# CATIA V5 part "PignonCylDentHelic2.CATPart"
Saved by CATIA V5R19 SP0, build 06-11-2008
Part number: Roue Cyl Denture Hélicoïdale.1
Bounding box of the stored display mesh (mm): x -31.113 to 31.113, y -31.287 to 31.287, z 0 to 88
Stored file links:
  C:\Users\Martin\Documents\IFMA\Cfao\Projet S3\PignonCylDentHelic2.CATPart
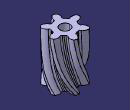
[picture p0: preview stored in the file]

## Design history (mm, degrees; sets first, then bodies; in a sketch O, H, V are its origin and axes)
External parameters (linked from other documents)
  External.Module = 7 mm
  External.Z = 6
  External.DiamPrimitif = 48.4974 mm {= External.ModuleApparent*External.Z}
  External.AnglePression = 20 deg
  External.x = 0
  External.DeportDenture = 0 mm {= External.x *External.ModuleApparent}
  External.DiamBase = 45.5727 mm {= External.DiamPrimitif *cos(External.AnglePression )}
  External.DiamPied = 38 mm
  External.DiamTete = 62.4974 mm {= External.DiamPrimitif +2*External.Module +2*External.DeportDenture}
  External.PhiPrimitif = 0.854 deg {= atan((sin(External.ThetaPrimitif*1rad)-External.ThetaPrimitif*cos(External.ThetaPrimitif*1rad))/(cos(External.ThetaPrimitif*1rad)+External.ThetaPrimitif*sin(External.ThetaPrimitif*1rad)))}
  External.PhiTete = 10.5878 deg {= atan((sin(External.ThetaTete*1rad)-External.ThetaTete*cos(External.ThetaTete*1rad))/(cos(External.ThetaTete*1rad)+External.ThetaTete*sin(External.ThetaTete*1rad)))}
  External.PhiSymetrie = 15 deg {= 180*1 deg/(2*External.Z )}
  External.CongePied = 2.66 mm {= 0.38*External.Module}
  External.AlphaCopie = 60 deg {= 360*1 deg/External.Z}
  External.AlphaSymetrieCopie = 30 deg {= External.AlphaCopie /2}
  External.LargeurDenture = 88 mm {= 88mm}
  External.ThetaPrimitif = 0.36397 {= sqrt(abs((External.DiamPrimitif*External.DiamPrimitif)/(External.DiamBase *External.DiamBase )-1))}
  External.ThetaTete = 0.938446 {= sqrt(abs((External.DiamTete*External.DiamTete)/(External.DiamBase *External.DiamBase )-1) )}
  External.Di = 47.035 mm {= (External.DiamBase +External.DiamPrimitif )/2}
  External.Thetai = 0.255358 {= sqrt(abs((External.Di*External.Di)/(External.DiamBase*External.DiamBase)-1))}
  External.Phii = 0.3061 deg {= atan((sin(External.Thetai*1rad)-External.Thetai*cos(External.Thetai*1rad))/(cos(External.Thetai*1rad)+External.Thetai*sin(External.Thetai*1rad)))}
  External.Dj = 55.4974 mm {= (External.DiamTete+External.DiamPrimitif)/2}
  External.Thetaj = 0.694971 {= sqrt(abs((External.Dj*External.Dj)/(External.DiamBase*External.DiamBase)-1))}
  External.Phij = 5.0207 deg {= atan((sin(External.Thetaj*1rad)-External.Thetaj*cos(External.Thetaj*1rad))/(cos(External.Thetaj*1rad)+External.Thetaj*sin(External.Thetaj*1rad)))}
  External.Dk = 46.3039 mm {= (External.Di+External.DiamBase)/2}
  External.Thetak = 0.179851 {= sqrt(abs((External.Dk*External.Dk)/(External.DiamBase*External.DiamBase)-1))}
  External.Phik = 0.109 deg {= atan((sin(External.Thetak*1rad)-External.Thetak*cos(External.Thetak*1rad))/(cos(External.Thetak*1rad)+External.Thetak*sin(External.Thetak*1rad)))}
  External.Dl = 47.7662 mm {= (External.DiamPrimitif+External.Di)/2}
  External.Thetal = 0.31398 {= sqrt(abs((External.Dl*External.Dl)/(External.DiamBase*External.DiamBase)-1))}
  External.Phil = 0.5585 deg {= atan((sin(External.Thetal*1rad)-External.Thetal*cos(External.Thetal*1rad))/(cos(External.Thetal*1rad)+External.Thetal*sin(External.Thetal*1rad)))}
  External.Dm = 51.9974 mm {= (External.Dj+External.DiamPrimitif)/2}
  External.Thetam = 0.549392 {= sqrt(abs((External.Dm*External.Dm)/(External.DiamBase*External.DiamBase)-1))}
  External.Phim = 2.6938 deg {= atan((sin(External.Thetam*1rad)-External.Thetam*cos(External.Thetam*1rad))/(cos(External.Thetam*1rad)+External.Thetam*sin(External.Thetam*1rad)))}
  External.Dn = 58.9974 mm {= (External.DiamTete+External.Dj)/2}
  External.Thetan = 0.822153 {= sqrt(abs((External.Dn*External.Dn)/(External.DiamBase*External.DiamBase)-1))}
  External.Phin = 7.6805 deg {= atan((sin(External.Thetan*1rad)-External.Thetan*cos(External.Thetan*1rad))/(cos(External.Thetan*1rad)+External.Thetan*sin(External.Thetan*1rad)))}
  External.AngleHelice = 30 deg
  External.ModuleApparent = 8.0829 mm {= External.Module /cos(External.AngleHelice )}
  External.SensDenture = -1
  External.LargeurDent = 45 mm {= round(PI*External.Module /sin(External.AngleHelice )/1mm)*1mm+1mm}
Body1 (main body)
  Sketch1 "EsquisseDent" on xy-plane, origin (0, 0, 0), H (1, 0, 0), V (0, 1, 0)
    construction circle A1 centre (0, 0) radius 24.2487
    construction circle A2 centre (0, 0) radius 22.7863
    construction circle A3 centre (0, 0) radius 19
    construction circle A4 centre (0, 0) radius 31.2487
    point P1 (22.7863, 0)
    construction line L1 (22.7863, 0) -> (0, 0)
    point P2 (24.246, 0.3614)
    construction line L2 (24.246, 0.3614) -> (0, 0)
    point P3 (30.7167, 5.7417)
    construction line L3 (30.7167, 5.7417) -> (0, 0)
    construction line L4 (22.7863, 0) -> (22.7863, 3.9367)
    point P4 (22.7863, 0)
    point P6 (21.3267, 0.3614)
    construction line L5 (30.7167, 5.7417) -> (24.246, 0.3614)
    point P7 (27.4814, 3.0515)
    point P8 (18.0913, 3.0515)
    spline S1 through (18.0913, 3.0515) (21.3267, 0.3614) (22.7863, 0) (23.1519, 0.044) (23.5172, 0.1257) (23.882, 0.2328) (24.246, 0.3614) (25.97, 1.2219) (27.6422, 2.4285) (29.2341, 3.9424) (30.7167, 5.7417)
    construction line L6 (0, 0) -> (5.0738, 1.4409)
    spline S2 through (16.9948, 6.9125) (18.3334, 10.9016) (19.3852, 11.9763) (19.7194, 12.1309) (20.073, 12.2535) (20.4397, 12.3541) (20.817, 12.436) (22.7359, 12.61) (24.7927, 12.4625) (26.9427, 12.0111) (29.1496, 11.2597)
    arc A5 centre (21.5111, -2.5354) radius 2.66 from (22.1075, 0.0569) to (18.8694, -2.224) ccw
    point P11 (18.8694, -2.224)
    arc A6 centre (0, 0) radius 31.2487 from (30.7167, 5.7417) to (29.1496, 11.2597) ccw
    point P13 (29.1496, 11.2597)
    arc A7 centre (16.9678, 13.4629) radius 2.66 from (14.884, 11.8096) to (18.8376, 11.571) ccw
    point P15 (14.884, 11.8096)
    construction line L7 (0, 0) -> (2.9832, 3.0735)
    construction line L8 (0, 0) -> (4.9704, -1.2527)
    point P19 (13.2333, 13.6338)
    arc A8 centre (0, 0) radius 19 from (14.884, 11.8096) to (13.2333, 13.6338) ccw
    point P20 (18.4238, -4.6435)
    arc A9 centre (0, 0) radius 19 from (18.4238, -4.6435) to (18.8694, -2.224) ccw
    line L9 (13.2333, 13.6338) -> (0, 0)
    line L10 (18.4238, -4.6435) -> (0, 0)
    construction circle A10 centre (0, 0) radius 23.5175
    construction line L11 (0, 0) -> (2.5698, 0.0137)
    point P22 (23.5172, 0.1257)
    construction circle A11 centre (0, 0) radius 27.7487
    construction line L12 (0, 0) -> (4.0036, 0.3517)
    point P24 (27.6422, 2.4285)
    point P25 (27.6422, 2.4285)
    point P26 (24.7927, 12.4625)
    point P27 (20.073, 12.2535)
    construction circle A12 centre (0, 0) radius 23.1519
    construction line L13 (0, 0) -> (48.2618, 0.0918)
    point P29 (19.7194, 12.1309)
    construction line L14 (0, 0) -> (61.5448, 17.478)
    point P31 (23.1519, 0.044)
    construction circle A13 centre (0, 0) radius 23.8831
    construction line L15 (0, 0) -> (57.3607, 0.5591)
    point P33 (23.882, 0.2328)
    point P34 (20.4397, 12.3541)
    construction circle A14 centre (0, 0) radius 25.9987
    construction line L16 (0, 0) -> (65.6381, 3.0883)
    point P36 (25.97, 1.2219)
    point P37 (22.7359, 12.61)
    construction circle A15 centre (0, 0) radius 29.4987
    axis line L17 (0, 0) -> (58.8185, 7.9321)
    point P39 (26.9427, 12.0111)
    point P40 (29.2341, 3.9424)
    point P42 (18.0913, 3.0515)
    point P43 (21.3267, 0.3614)
    point P44 (22.7863, 0)
    point P45 (24.246, 0.3614)
    point P46 (30.7167, 5.7417)
    point P47 (29.1496, 11.2597)
    point P48 (16.9948, 6.9125)
    point P49 (20.817, 12.436)
    point P50 (19.3852, 11.9763)
    point P51 (18.3334, 10.9016)
    point P52 (23.5172, 0.1257)
    point P53 (27.6422, 2.4285)
    point P54 (20.073, 12.2535)
    point P55 (24.7927, 12.4625)
    point P56 (23.1519, 0.044)
    point P57 (19.7194, 12.1309)
    point P58 (23.882, 0.2328)
    point P59 (20.4397, 12.3541)
    point P60 (25.97, 1.2219)
    point P61 (22.7359, 12.61)
    point P62 (29.2341, 3.9424)
    point P63 (26.9427, 12.0111)
    radius A1 = 24.2487 {= External.DiamPrimitif /2}
    radius A2 = 22.7863 {= External.DiamBase /2}
    radius A3 = 19 {= External.DiamPied /2}
    radius A4 = 31.2487 {= External.DiamTete /2}
    angle L2 L1 = 0.854 {= External.PhiPrimitif}
    angle L3 L1 = 10.5878 {= External.PhiTete}
    angle L4 L1 = 90
    radius A5 = 2.66 {= External.CongePied}
    radius A7 = 2.66 {= External.CongePied}
    angle L7 L6 = 30 {= External.AlphaSymetrieCopie}
    angle L2 L6 = 15 {= External.PhiSymetrie}
    radius A10 = 23.5175 {= External.Di /2}
    angle L11 L1 = 0.3061 {= External.Phii}
    radius A11 = 27.7487 {= External.Dj /2}
    angle L12 L1 = 5.0207 {= External.Phij}
    radius A12 = 23.1519 {= External.Dk/2}
    angle L13 L1 = 0.109 {= External.Phik}
    angle L14 L2 = 15 {= External.PhiSymetrie}
    radius A13 = 23.8831 {= External.Dl /2}
    angle L15 L1 = 0.5585 {= External.Phil}
    radius A14 = 25.9987 {= External.Dm /2}
    angle L16 L1 = 2.6938 {= External.Phim}
    radius A15 = 29.4987 {= External.Dn/2}
    angle L17 L1 = 7.6805 {= External.Phin}
    coincidence: P1 A2, P1 H, P2 A1, P3 A4, P4 A2, P7 L5, P42 P8, P43 P6, P44 P1, P45 L5, P45 L2, P46 L5, P46 L3, P11 A3, P47 P13, P15 A3, P19 L7, P19 A3, P20 L8, P20 A3, P3 P46, P22 L11, P22 A10, P52 P22, P24 L12, P24 A11, P53 P24, P25 P53, P54 P27, P55 P26, P31 L13, P31 A12, P56 P31, P57 P29, P33 L15, P33 A13, P58 P33, P59 P34, P36 L16, P36 A14, P60 P36, P61 P37, P40 L17, P40 A15, P62 P40, P63 P39, O L9, O L10
    horizontal: L1 H
    tangency: L4 A2, A5 A3, A5 S1, A7 A3, A7 S2, A8 A5, A9 A5
    symmetry: P6 P2 L4, P8 P7 L4, P46 P47 L6, P42 P48 L6, P45 P49 L6, P44 P50 L6, P43 P51 L6, L8 L7 L6, P26 P25 L6, P27 P22 L6, P29 P31 L14, P34 P33 L14, P37 P36 L14, P39 P40 L14
    midpoint: P7 L5
    parallelism: L9 L7, L10 L8
    concentricity: A10 A2, A11 A1
  Translate1: Length 88 {= External.LargeurDenture}, Direction (0, 0, 1), ToTransfor Sketch1
  Rotate1: Axis Z axis, Angle -64.4861 {= External.SensDenture *atan(2*External.LargeurDenture/External.DiamPrimitif*tan(External.AngleHelice))}, ToTransfor Translate1
  Translate2: Length 44 {= External.LargeurDenture/2}, Direction (0, 0, 1), ToTransfor Sketch1
  Rotate2: Axis Z axis, Angle -46.3322 {= External.SensDenture *atan(External.LargeurDenture/(External.DiamPrimitif)*tan(External.AngleHelice))}, ToTransfor Translate2
  Translate3: Length 66 {= 3/4*External.LargeurDenture}, Direction (0, 0, 1), ToTransfor Sketch1
  Rotate3: Axis Z axis, Angle -57.5288 {= External.SensDenture*atan(3*External.LargeurDenture/(2*External.DiamPrimitif)*tan(External.AngleHelice))}, ToTransfor Translate3
  Translate4: Length 22 {= External.LargeurDenture/4}, Direction (0, 0, 1), ToTransfor Sketch1
  Rotate4: Axis Z axis, Angle -27.646 {= External.SensDenture*atan(External.LargeurDenture/(2*External.DiamPrimitif)*tan(External.AngleHelice))}, ToTransfor Translate4
  Loft1: solid, Sections (Sketch1; Rotate4; Rotate2; Rotate3; Rotate1)
  CircPattern1: of the body so far, instances 6 {= External.Z}, angular step 60 {= External.AlphaCopie}, axis from Z axis
  Plane1: type Offset, Offset 88 {= External.LargeurDenture}, RefPlane xy-plane, reversed
  Sketch2 on Plane1, origin (0, 0, -88), H (1, 0, 0), V (0, 1, 0)
    circle A1 centre (0, 0) radius 9
    radius A1 = 9 {= int(External.DiamPied/(4mm))*1mm}
  Pocket1: profile Sketch2, direction (0, 0, 1), length 264 {= 3*External.LargeurDenture}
